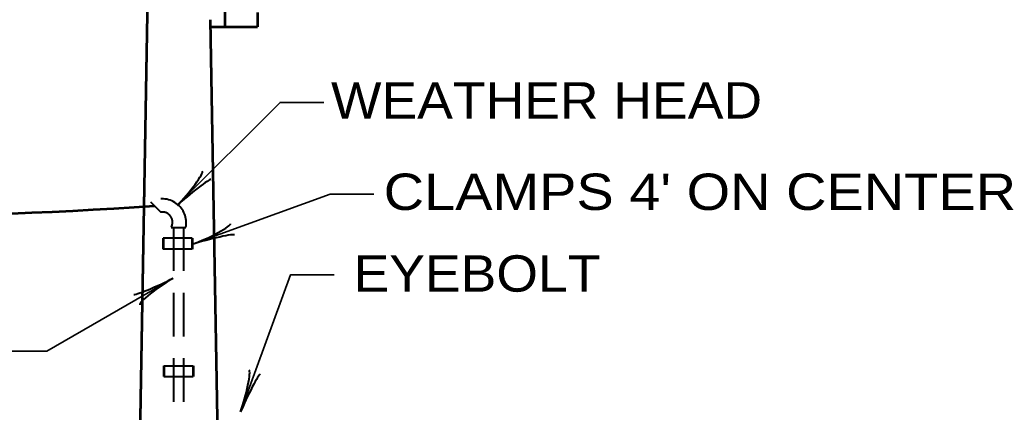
# Model space of a CAD drawing. Extents: x 12366 to 13046, y 9129 to 9570.
# Drawn here: x 12453.9 to 12521.7, y 9505.7 to 9532.7 of the extents above; entities that cross this region are included whole.
import ezdxf

# ---------------------------------------------------------------- set-up
doc = ezdxf.new("R2010")
doc.units = 0
doc.linetypes.add('MEDIUM_DASHED', pattern=[4.5, 3, -1.5])
doc.layers.add('1', color=7, linetype='Continuous', lineweight=53)

msp = doc.modelspace()

# ---------------------------------------------------------------- linework, layer by layer
at = {"layer": '1'}
for p, q in [((12462.852, 9542.164), (12460.844, 9427.165)), ((12462.852, 9542.164), (12460.844, 9427.137)), ((12462.852, 9542.164), (12460.844, 9427.133)), ((12468.026, 9535.189), (12468.026, 9532.189)), ((12467.017, 9532.683), (12467.018, 9532.655)), ((12470.276, 9533.189), (12470.276, 9532.189)), ((12467.018, 9532.655), (12469.434, 9394.187)), ((12467.018, 9532.655), (12469.382, 9397.186)), ((12467.018, 9532.655), (12469.382, 9397.186)), ((12467.026, 9532.189), (12468.026, 9532.189)), ((12468.026, 9532.189), (12470.276, 9532.189))]:
    msp.add_line(p, q, dxfattribs=at)
at = {"layer": '1', "linetype": 'MEDIUM_DASHED', "lineweight": 40}
for p, q in [((12462.923, 9520.166), (12463.63, 9519.459)), ((12464.352, 9518.414), (12465.352, 9518.414)), ((12464.502, 9518.414), (12464.502, 9503.414)), ((12465.202, 9518.414), (12465.202, 9503.414)), ((12465.798, 9517.664), (12463.798, 9517.664)), ((12465.798, 9516.914), (12463.798, 9516.914)), ((12463.852, 9508.903), (12465.852, 9508.903)), ((12463.852, 9508.153), (12465.852, 9508.153))]:
    msp.add_line(p, q, dxfattribs=at)
at = {"layer": '1', "linetype": 'MEDIUM_DASHED'}
for p, q in [((12463.798, 9517.664), (12463.798, 9516.914)), ((12465.798, 9517.664), (12465.798, 9516.914)), ((12463.852, 9508.903), (12463.852, 9508.153)), ((12465.852, 9508.903), (12465.852, 9508.153))]:
    msp.add_line(p, q, dxfattribs=at)
at = {"layer": '1', "lineweight": 35}
for points in [[(12464.759, 9519.933), (12471.83, 9527.005), (12474.83, 9527.005)], [(12465.867, 9517.273), (12475.264, 9520.693), (12478.264, 9520.693)], [(12469.119, 9505.743), (12472.539, 9515.14), (12475.539, 9515.14)], [(12464.463, 9514.908), (12455.803, 9509.908), (12452.803, 9509.908)]]:
    msp.add_lwpolyline(points, dxfattribs=at)
at = {"layer": '1'}
msp.add_arc((12440.705, 9851.581), 332.455, 266.11935, 273.88065, dxfattribs=at)
at = {"layer": '1', "linetype": 'MEDIUM_DASHED', "lineweight": 40}
for centre, radius, start, end in [((12463.723, 9518.716), 1.656, 349.50124, 118.8707), ((12463.733, 9518.759), 0.708, 330.86779, 98.35179)]:
    msp.add_arc(centre, radius, start, end, dxfattribs=at)
at = {"layer": '1', "lineweight": 40}
for centre, major_axis, ratio, start_param, end_param in [((12465.335, 9520.9), (-1.152, -1.373), 0.122415, 0.896353, 3.141593), ((12465.701, 9520.576), (1.366, 1.118), 0.07063, 6.282307, 8.559703), ((12466.798, 9517.906), (-1.625, -0.757), 0.122415, 0.896353, 3.141593), ((12466.992, 9517.457), (1.711, 0.436), 0.07063, 6.282307, 8.559703), ((12463.387, 9514.531), (-1.609, -0.726), 0.07063, 6.282307, 8.559703), ((12463.656, 9514.123), (1.468, 1.028), 0.122415, 0.896353, 3.141593), ((12469.233, 9506.863), (-0.464, -1.731), 0.122415, 0.896353, 3.141593), ((12469.701, 9506.723), (0.766, 1.59), 0.07063, 6.282307, 8.559703)]:
    msp.add_ellipse(centre, major_axis=major_axis, ratio=ratio, start_param=start_param, end_param=end_param, dxfattribs=at)

# ---------------------------------------------------------------- texts
at = {"layer": '1'}
for s, width, p in [('WEATHER HEAD', 1.1, (12475.328, 9525.89)), ("CLAMPS 4' ON CENTER", 1.15, (12478.949, 9519.608)), ('EYEBOLT', 1.1, (12476.88, 9513.991))]:
    msp.add_text(s, height=2.5, dxfattribs=dict(at, width=width)).set_placement(p)

doc.saveas('drawing.dxf')
